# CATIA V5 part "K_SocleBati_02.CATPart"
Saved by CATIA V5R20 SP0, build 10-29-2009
Part number: Socle_bati_02
Bounding box of the stored display mesh (mm): x 0 to 25, y -279.606 to -5, z -40 to 40
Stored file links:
  G:\Khaled_CFAO_2011\ST2M\ST2M_GR2\jcoetard\Khaled\CAD_CATIA\K_SocleBati_02.CATPart
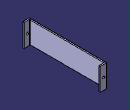
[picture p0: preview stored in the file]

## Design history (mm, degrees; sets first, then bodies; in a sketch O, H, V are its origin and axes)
Set1 "Set géométrique"
  Point1: type OnSurface, Support face of Pad2, Length 0, Direction (-0.2061, 0, -0.9785)
Body1 (main body)
  Sketch1 on yz-plane, origin (0, 0, 0), H (0, 1, 0), V (0, 0, 1)
    line L1 (-279.606, 40) -> (-5, 40)
    line L2 (-5, 40) -> (-5, -40)
    line L3 (-5, -40) -> (-279.606, -40)
    line L4 (-279.606, -40) -> (-279.606, 40)
    construction line L5 (-284.606, 180.3057) -> (-284.606, -158.6943)
    construction line L6 (0, 143) -> (0, -221)
    point P7 (0, 143)
    axis line L7 (-369, 0) -> (267, 0)
    point P9 (-369, 0)
    distance L4 L5 = 5
    distance L2 L6 = 5
    distance L5 L6 = 284.606
    distance L1 L3 = 80
    distance L1 L7 = 40
    horizontal: L1 H, L3 H, L7 H
    vertical: L2 V, L4 V, L5 V, L6 V
    coincidence: P7 V, P9 H
  Pad1: profile Sketch1, direction (1, 0, 0), length 5
  Sketch2 on end face of Pad1, origin (5, 0, 0), H (0, 1, 0), V (0, 0, 1)
    line L1 (-10, 40) -> (-5, 40)
    line L2 (-5, 40) -> (-5, -40)
    line L3 (-5, -40) -> (-10, -40)
    line L4 (-10, -40) -> (-10, 40)
    reference projected line E1 (-5, -40) -> (-5, 40) from edge [face of Pad1 from Sketch1.L2 | end face of Pad1]
    reference projected line E2 (-5, 40) -> (-279.606, 40) from edge [face of Pad1 from Sketch1.L1 | end face of Pad1]
    reference projected line E3 (-279.606, -40) -> (-5, -40) from edge [face of Pad1 from Sketch1.L3 | end face of Pad1]
    line L5 (-279.606, 40) -> (-274.606, 40)
    line L6 (-274.606, 40) -> (-274.606, -40)
    line L7 (-274.606, -40) -> (-279.606, -40)
    line L8 (-279.606, -40) -> (-279.606, 40)
    reference projected line E4 (-5, 40) -> (-279.606, 40) from edge [face of Pad1 from Sketch1.L1 | end face of Pad1]
    reference projected line E5 (-279.606, -40) -> (-5, -40) from edge [face of Pad1 from Sketch1.L3 | end face of Pad1]
    reference projected line E6 (-279.606, 40) -> (-279.606, -40) from edge [face of Pad1 from Sketch1.L4 | end face of Pad1]
    distance L4 L2 = 5
    distance L8 L6 = 5
    horizontal: L1 H, L3 H, L5 H, L7 H
    vertical: L2 V, L4 V, L6 V, L8 V
    coincidence: L2 E1, L1 E2, L3 E3, L5 E4, L7 E5, L8 E6
  Pad2: profile Sketch2, direction (1, 0, 0), length 20
  Sketch3 on face of Pad2, origin (5, -5, 0), H (1, 0, 0), V (0, 0, -1)
    point P1 (7.5, 0)
    reference projected point E1 (7.5, 0) from Point1
    coincidence: E1 P1
  Hole1: placed by Sketch3, at (12.5, -5, 0) direction (0, -1, 0), diameter 8, depth 400
  Fillet1: radius 2, on start face of Pad1; end face of Pad1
